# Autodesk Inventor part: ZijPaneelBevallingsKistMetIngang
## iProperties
Created: 2010-03
Part Number: ZijPaneelBevallingsKistMetIngang
Document SubType Name: Modeling
Designer: Ferry
Density: 1 g/cm^3
Author: Ferry
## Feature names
1. Extrusion1
2. Extrusion2
3. Fillet1
4. Fillet2
5. Extrusion5
